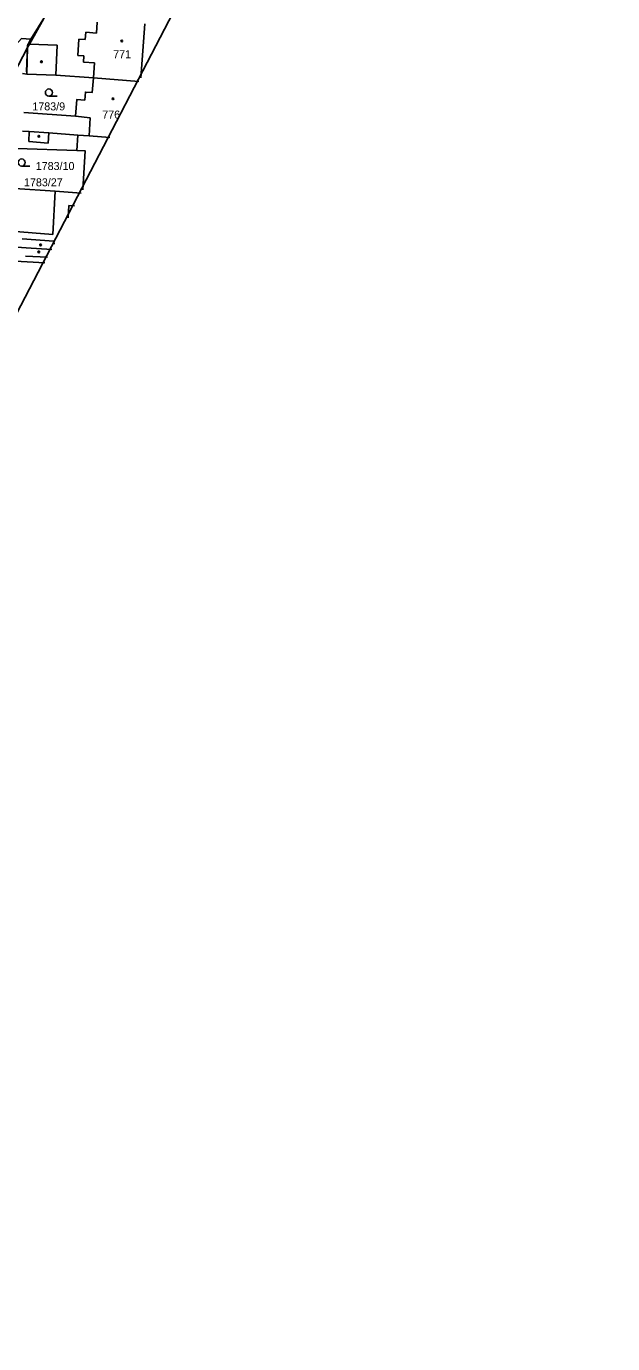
# Model space of a CAD drawing. Extents: x -781083 to -763634, y -1029516 to -1022695.
# Drawn here: x -765088.2 to -764963.8, y -1024432.1 to -1024152.2 of the extents above; entities that cross this region are included whole.
import ezdxf

# ---------------------------------------------------------------- set-up
doc = ezdxf.new("R2010")
doc.units = 0
for name, color, linetype in [('Hranice parcel', 7, 'Continuous'), ('Parcelní čísla', 7, 'Continuous'), ('Vnitřní kresba', 7, 'Continuous'), ('Vrstva 16', 7, 'Continuous'), ('Vrstva 17', 7, 'Continuous'), ('Značky budov', 7, 'Continuous'), ('Značky kultur', 7, 'Continuous')]:
    doc.layers.add(name, color=color, linetype=linetype)

# ---------------------------------------------------------------- blocks, each defined once
blk = doc.blocks.new('4.02')
at = {"layer": 'Značky budov'}
blk.add_circle((-0.1, 0), 1.75, dxfattribs=at)
blk = doc.blocks.new('3.04')
at = {"layer": 'Značky kultur'}
blk.add_line((0.1, 0), (17.6, 0), dxfattribs=at)
blk.add_circle((0.1, 7.5), 7.5, dxfattribs=at)

msp = doc.modelspace()

# ---------------------------------------------------------------- linework, layer by layer
msp.add_lwpolyline([(-765336.12, -1024363.48), (-765204.05, -1024432.09), (-764769.73, -1023596.11), (-764901.79, -1023527.49)], close=True)
at = {"layer": 'Hranice parcel'}
for p, q in [((-765063.91, -1024163.18), (-765063.08, -1024151.69)), ((-765073.97, -1024163.19), (-765064.32, -1024163.97))]:
    msp.add_line(p, q, dxfattribs=at)
for points in [[(-765084.49, -1024150.57), (-765087.56, -1024156.04), (-765087.96, -1024156.74), (-765090.9, -1024162.29)], [(-765089.05, -1024162.27), (-765088.16, -1024162.39), (-765081.94, -1024162.62), (-765073.97, -1024163.19)], [(-765073.97, -1024163.19), (-765074.27, -1024166.32), (-765075.68, -1024166.2), (-765075.83, -1024167.9), (-765077.5, -1024167.75), (-765077.82, -1024171.31), (-765088.8, -1024170.52)], [(-765089.03, -1024174.49), (-765087.61, -1024174.59), (-765083.48, -1024174.88), (-765077.29, -1024175.33), (-765074.9, -1024175.5), (-765070.48, -1024175.82)], [(-765090.16, -1024178.17), (-765077.5, -1024178.6), (-765075.75, -1024178.66), (-765076.27, -1024186.96)], [(-765076.62, -1024187.64), (-765082.13, -1024187.28), (-765090.68, -1024186.71)], [(-765091.62, -1024199.08), (-765089.24, -1024199.23), (-765088.3, -1024199.29), (-765082.85, -1024199.63)]]:
    msp.add_lwpolyline(points, dxfattribs=at)
at = {"layer": 'Vnitřní kresba'}
for p, q in [((-765075.74, -1024155.06), (-765075.61, -1024153.5)), ((-765075.61, -1024153.5), (-765073.31, -1024153.66)), ((-765073.31, -1024153.66), (-765073.18, -1024151.38)), ((-765087.93, -1024156.03), (-765087.96, -1024156.74)), ((-765087.93, -1024156.03), (-765087.56, -1024156.04)), ((-765087.56, -1024156.04), (-765081.7, -1024156.23)), ((-765081.7, -1024156.23), (-765081.94, -1024162.62)), ((-765077.31, -1024158.45), (-765077.11, -1024154.99)), ((-765077.11, -1024154.99), (-765075.74, -1024155.06)), ((-765087.96, -1024156.74), (-765088.16, -1024162.39)), ((-765076.05, -1024158.53), (-765077.31, -1024158.45)), ((-765076.13, -1024159.87), (-765076.05, -1024158.53)), ((-765073.78, -1024160.01), (-765076.13, -1024159.87)), ((-765073.97, -1024163.19), (-765073.78, -1024160.01)), ((-765077.82, -1024171.31), (-765074.69, -1024171.68)), ((-765074.69, -1024171.68), (-765074.9, -1024175.5)), ((-765087.61, -1024174.59), (-765087.74, -1024176.73)), ((-765083.6, -1024177.04), (-765083.48, -1024174.88)), ((-765077.29, -1024175.33), (-765077.5, -1024178.6)), ((-765087.74, -1024176.73), (-765083.6, -1024177.04)), ((-765082.13, -1024187.28), (-765082.58, -1024196.46)), ((-765079.38, -1024192.95), (-765079.21, -1024190.29)), ((-765079.21, -1024190.29), (-765078.03, -1024190.36)), ((-765091.36, -1024195.72), (-765082.58, -1024196.46)), ((-765089.12, -1024197.4), (-765082.39, -1024197.89)), ((-765082.39, -1024197.89), (-765082.42, -1024198.34)), ((-765082.42, -1024198.34), (-765082.19, -1024198.36)), ((-765088.41, -1024201.05), (-765083.72, -1024201.3)), ((-765084.34, -1024202.49), (-765091.83, -1024202.08))]:
    msp.add_line(p, q, dxfattribs=at)
at = {"layer": 'Vrstva 16'}
for points in [[(-765096.09, -1024155.11), (-765093.89, -1024156.66), (-765091.02, -1024156.79), (-765089.28, -1024154.83), (-765087.25, -1024154.99)], [(-765088.23, -1024161.9), (-765088.01, -1024156.3)], [(-765088.01, -1024156.3), (-765087.25, -1024154.99)]]:
    msp.add_lwpolyline(points, dxfattribs=at)
at = {"layer": 'Vrstva 17'}
msp.add_lwpolyline([(-765087.25, -1024154.99), (-765084.39, -1024150.31)], dxfattribs=at)

# ---------------------------------------------------------------- block references
at = {"layer": 'Značky budov', "xscale": 0.1, "yscale": 0.10000000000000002}
for p in [(-765067.97, -1024155.36), (-765085.02, -1024159.77), (-765069.81, -1024167.62), (-765085.57, -1024175.59), (-765085.21, -1024198.66), (-765085.58, -1024200.15)]:
    msp.add_blockref('4.02', p, dxfattribs=at)
at = {"layer": 'Značky kultur', "xscale": 0.1, "yscale": 0.10000000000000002}
for p in [(-765083.46, -1024167.04), (-765089.24, -1024181.91)]:
    msp.add_blockref('3.04', p, dxfattribs=at)

# ---------------------------------------------------------------- texts
at = {"layer": 'Parcelní čísla'}
for s, p in [('771', (-765069.8, -1024159)), ('1783/9', (-765086.96, -1024170.09)), ('776', (-765072.12, -1024171.83)), ('1783/10', (-765086.24, -1024182.76)), ('1783/27', (-765088.73, -1024186.22))]:
    msp.add_text(s, height=1.7, dxfattribs=at).set_placement(p)

doc.saveas('drawing.dxf')
